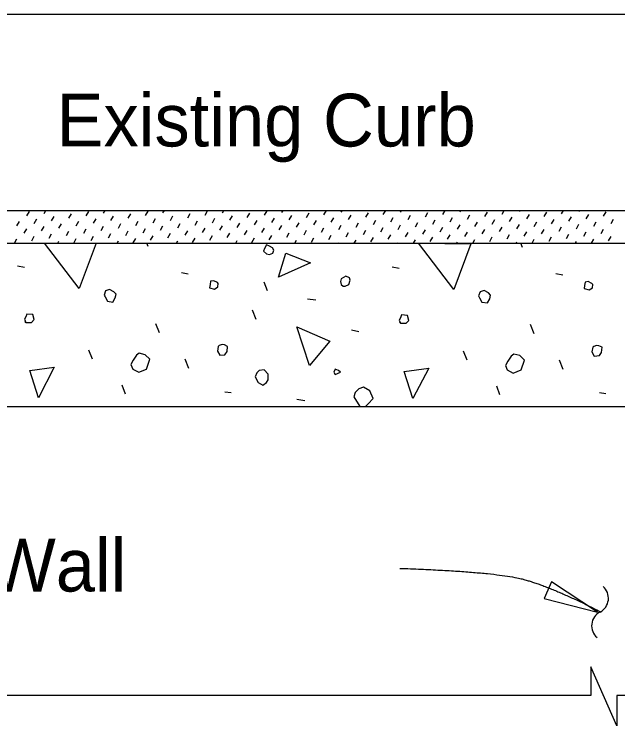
# Model space of a CAD drawing. Extents: x 2.6 to 35.7, y 1.7 to 23.4.
# Drawn here: x 11.926 to 14.234, y 5.942 to 8.663 of the extents above; entities that cross this region are included whole.
import ezdxf

# ---------------------------------------------------------------- set-up
doc = ezdxf.new("R2010")
doc.units = 0
for name, color, linetype in [('Dimension', 7, 'Continuous'), ('Miscellaneous', 7, 'Continuous'), ('TextStructures', 7, 'Continuous'), ('TrafBarrierConc', 7, 'Continuous')]:
    doc.layers.add(name, color=color, linetype=linetype)

msp = doc.modelspace()

# ---------------------------------------------------------------- linework, layer by layer
at = {"layer": 'Dimension'}
msp.add_lwpolyline([(14.1568, 6.3768), (13.9806, 6.4933), (13.952, 6.4288)], close=True, dxfattribs=at)
for points in [[(12.6311, 6.0586), (10.0672, 6.0586), (10.0672, 5.9424), (9.9678, 6.1674), (9.9678, 6.0586), (8.3596, 6.0586)], [(17.7044, 6.0586), (14.2297, 6.0586), (14.2297, 5.9424), (14.1304, 6.1674), (14.1304, 6.0586), (12.6311, 6.0586)]]:
    msp.add_lwpolyline(points, dxfattribs=at)
for centre, start, end in [((14.1386, 6.4303), 297.3915, 49.1187), ((14.1935, 6.3245), 117.3915, 229.1187)]:
    msp.add_arc(centre, 0.0596, start, end, dxfattribs=at)
msp.add_open_spline([(13.4009, 6.5444), (13.7659, 6.5314), (13.982, 6.4729), (14.1657, 6.3795)], degree=2, dxfattribs=at)
at = {"layer": 'Miscellaneous'}
for p, q in [((11.9745, 7.8919), (11.9842, 7.9087)), ((12.0408, 7.9016), (12.0476, 7.9134)), ((12.1071, 7.9113), (12.1083, 7.9134)), ((12.1354, 7.8831), (12.1451, 7.8999)), ((12.2017, 7.8928), (12.2114, 7.9096)), ((12.268, 7.9025), (12.2743, 7.9134)), ((12.3343, 7.9122), (12.3349, 7.9134)), ((12.3626, 7.8839), (12.3723, 7.9007)), ((12.4288, 7.8937), (12.4386, 7.9105)), ((12.4951, 7.9034), (12.5009, 7.9134)), ((12.5234, 7.8751), (12.5331, 7.8919)), ((12.5614, 7.9131), (12.5616, 7.9134)), ((12.5897, 7.8848), (12.5994, 7.9016)), ((12.656, 7.8946), (12.6657, 7.9113)), ((12.7223, 7.9043), (12.7276, 7.9134)), ((12.7506, 7.876), (12.7603, 7.8928)), ((12.8169, 7.8857), (12.8266, 7.9025)), ((12.8832, 7.8954), (12.8929, 7.9122)), ((12.9494, 7.9052), (12.9542, 7.9134)), ((12.9777, 7.8769), (12.9875, 7.8937)), ((13.044, 7.8866), (13.0537, 7.9034)), ((13.1103, 7.8963), (13.12, 7.9131)), ((13.1766, 7.906), (13.1809, 7.9134)), ((13.2049, 7.8778), (13.2146, 7.8946)), ((13.2712, 7.8875), (13.2809, 7.9043)), ((13.3375, 7.8972), (13.3469, 7.9134)), ((13.4038, 7.9069), (13.4075, 7.9134)), ((13.432, 7.8786), (13.4418, 7.8954)), ((13.4983, 7.8884), (13.5081, 7.9052)), ((13.5646, 7.8981), (13.5735, 7.9134)), ((13.6309, 7.9078), (13.6342, 7.9134)), ((13.6592, 7.8795), (13.6689, 7.8963)), ((13.7255, 7.8893), (13.7352, 7.906)), ((13.7918, 7.899), (13.8001, 7.9134)), ((13.8581, 7.9087), (13.8608, 7.9134)), ((13.8864, 7.8804), (13.8961, 7.8972)), ((13.9527, 7.8901), (13.9624, 7.9069)), ((14.0189, 7.8999), (14.0268, 7.9134)), ((14.0852, 7.9096), (14.0875, 7.9134)), ((14.1135, 7.8813), (14.1232, 7.8981)), ((14.1798, 7.891), (14.1895, 7.9078)), ((11.9365, 7.8539), (11.9462, 7.8707)), ((12.0028, 7.8636), (12.0125, 7.8804)), ((12.0691, 7.8733), (12.0788, 7.8901)), ((12.1637, 7.8548), (12.1734, 7.8716)), ((12.23, 7.8645), (12.2397, 7.8813)), ((12.2963, 7.8742), (12.306, 7.891)), ((12.3908, 7.8557), (12.4006, 7.8725)), ((12.4571, 7.8654), (12.4668, 7.8822)), ((12.618, 7.8565), (12.6277, 7.8733)), ((12.6843, 7.8663), (12.694, 7.8831)), ((12.7789, 7.8477), (12.7886, 7.8645)), ((12.8452, 7.8574), (12.8549, 7.8742)), ((12.9114, 7.8672), (12.9212, 7.8839)), ((13.006, 7.8486), (13.0157, 7.8654)), ((13.0723, 7.8583), (13.082, 7.8751)), ((13.1386, 7.868), (13.1483, 7.8848)), ((13.2332, 7.8495), (13.2429, 7.8663)), ((13.2995, 7.8592), (13.3092, 7.876)), ((13.3658, 7.8689), (13.3755, 7.8857)), ((13.4603, 7.8504), (13.4701, 7.8672)), ((13.5266, 7.8601), (13.5363, 7.8769)), ((13.5929, 7.8698), (13.6026, 7.8866)), ((13.6875, 7.8512), (13.6972, 7.868)), ((13.7538, 7.861), (13.7635, 7.8778)), ((13.8201, 7.8707), (13.8298, 7.8875)), ((13.9147, 7.8521), (13.9244, 7.8689)), ((13.9809, 7.8619), (13.9907, 7.8786)), ((14.0472, 7.8716), (14.057, 7.8884)), ((14.1418, 7.853), (14.1515, 7.8698)), ((14.2081, 7.8627), (14.2178, 7.8795)), ((11.9648, 7.8256), (11.9745, 7.8424)), ((12.0311, 7.8353), (12.0408, 7.8521)), ((12.0974, 7.8451), (12.1071, 7.8619)), ((12.192, 7.8265), (12.2017, 7.8433)), ((12.2583, 7.8362), (12.268, 7.853)), ((12.3245, 7.8459), (12.3343, 7.8627)), ((12.4191, 7.8274), (12.4288, 7.8442)), ((12.4854, 7.8371), (12.4951, 7.8539)), ((12.5517, 7.8468), (12.5614, 7.8636)), ((12.6463, 7.8283), (12.656, 7.8451)), ((12.7126, 7.838), (12.7223, 7.8548)), ((12.8734, 7.8291), (12.8832, 7.8459)), ((12.9397, 7.8389), (12.9494, 7.8557)), ((13.0343, 7.8203), (13.044, 7.8371)), ((13.1006, 7.83), (13.1103, 7.8468)), ((13.1669, 7.8398), (13.1766, 7.8565)), ((13.2615, 7.8212), (13.2712, 7.838)), ((13.3278, 7.8309), (13.3375, 7.8477)), ((13.394, 7.8406), (13.4038, 7.8574)), ((13.4886, 7.8221), (13.4983, 7.8389)), ((13.5549, 7.8318), (13.5646, 7.8486)), ((13.6212, 7.8415), (13.6309, 7.8583)), ((13.7158, 7.823), (13.7255, 7.8398)), ((13.7821, 7.8327), (13.7918, 7.8495)), ((13.8484, 7.8424), (13.8581, 7.8592)), ((13.9429, 7.8238), (13.9527, 7.8406)), ((14.0092, 7.8336), (14.0189, 7.8504)), ((14.0755, 7.8433), (14.0852, 7.8601)), ((14.1701, 7.8247), (14.1798, 7.8415)), ((11.9931, 7.7973), (12.0028, 7.8141)), ((12.0594, 7.807), (12.0691, 7.8238)), ((12.1257, 7.8168), (12.1354, 7.8336)), ((12.2202, 7.7982), (12.23, 7.815)), ((12.2865, 7.8079), (12.2963, 7.8247)), ((12.3528, 7.8177), (12.3626, 7.8345)), ((12.4474, 7.7991), (12.4571, 7.8159)), ((12.5137, 7.8088), (12.5234, 7.8256)), ((12.58, 7.8185), (12.5897, 7.8353)), ((12.6746, 7.8), (12.6843, 7.8168)), ((12.7409, 7.8097), (12.7506, 7.8265)), ((12.8071, 7.8194), (12.8169, 7.8362)), ((12.9017, 7.8009), (12.9114, 7.8177)), ((12.968, 7.8106), (12.9777, 7.8274)), ((13.1289, 7.8017), (13.1386, 7.8185)), ((13.1952, 7.8115), (13.2049, 7.8283)), ((13.2897, 7.7929), (13.2995, 7.8097)), ((13.356, 7.8026), (13.3658, 7.8194)), ((13.4223, 7.8124), (13.432, 7.8291)), ((13.5169, 7.7938), (13.5266, 7.8106)), ((13.5832, 7.8035), (13.5929, 7.8203)), ((13.6495, 7.8132), (13.6592, 7.83)), ((13.7441, 7.7947), (13.7538, 7.8115)), ((13.8104, 7.8044), (13.8201, 7.8212)), ((13.8766, 7.8141), (13.8864, 7.8309)), ((13.9712, 7.7956), (13.9809, 7.8124)), ((14.0375, 7.8053), (14.0472, 7.8221)), ((14.1038, 7.815), (14.1135, 7.8318)), ((14.1984, 7.7964), (14.2081, 7.8132)), ((11.9273, 7.7884), (11.9365, 7.8044)), ((12.0932, 7.7884), (12.0974, 7.7956)), ((12.154, 7.7885), (12.1637, 7.8053)), ((12.3199, 7.7884), (12.3245, 7.7964)), ((12.3811, 7.7894), (12.3908, 7.8062)), ((12.438, 7.775), (12.4331, 7.7884)), ((12.5465, 7.7884), (12.5517, 7.7973)), ((12.6083, 7.7903), (12.618, 7.807)), ((12.7125, 7.7884), (12.7126, 7.7885)), ((12.7732, 7.7884), (12.7789, 7.7982)), ((12.8354, 7.7911), (12.8452, 7.8079)), ((12.9392, 7.7884), (12.9397, 7.7894)), ((12.9998, 7.7884), (13.006, 7.7991)), ((13.0626, 7.792), (13.0723, 7.8088)), ((13.1658, 7.7884), (13.1669, 7.7903)), ((13.2265, 7.7884), (13.2332, 7.8)), ((13.3925, 7.7884), (13.394, 7.7911)), ((13.4531, 7.7884), (13.4603, 7.8009)), ((13.6191, 7.7884), (13.6212, 7.792)), ((13.6798, 7.7884), (13.6875, 7.8017)), ((13.8458, 7.7884), (13.8484, 7.7929)), ((13.8699, 7.7715), (13.8637, 7.7884)), ((13.9064, 7.7884), (13.9147, 7.8026)), ((14.0724, 7.7884), (14.0755, 7.7938)), ((14.1331, 7.7884), (14.1418, 7.8035)), ((11.9395, 7.7008), (11.966, 7.6955)), ((12.5653, 7.6761), (12.5918, 7.6707)), ((13.3714, 7.6973), (13.3979, 7.692)), ((13.9972, 7.6725), (14.0237, 7.6672)), ((12.8941, 7.6053), (12.8817, 7.6389)), ((13.0479, 7.5753), (13.0797, 7.5718)), ((12.8517, 7.4957), (12.8375, 7.5311)), ((12.4822, 7.4445), (12.4681, 7.4798)), ((13.2158, 7.4568), (13.2441, 7.4498)), ((13.9141, 7.4409), (13.9, 7.4763)), ((12.2259, 7.3437), (12.2117, 7.3791)), ((13.6578, 7.3402), (13.6436, 7.3755)), ((12.5936, 7.3084), (12.5794, 7.3437)), ((14.0255, 7.3048), (14.0113, 7.3402)), ((12.3514, 7.2111), (12.339, 7.2447)), ((13.7833, 7.2076), (13.7709, 7.2412)), ((12.7315, 7.22), (12.7562, 7.2164)), ((14.1634, 7.2164), (14.1881, 7.2129)), ((13.0072, 7.1917), (13.0373, 7.1864))]:
    msp.add_line(p, q, dxfattribs=at)
for points in [[(12.1746, 7.6142), (12.0422, 7.7884)], [(12.2397, 7.7884), (12.1746, 7.6142)], [(13.6065, 7.6106), (13.4722, 7.7874), (13.6719, 7.7857), (13.6065, 7.6106)], [(12.8906, 7.7468), (12.9029, 7.745), (12.9153, 7.7503), (12.9188, 7.7609), (12.9135, 7.7697), (12.9029, 7.7768), (12.8906, 7.7821), (12.8835, 7.768), (12.88, 7.7574), (12.8906, 7.7468)], [(12.9365, 7.6584), (12.9648, 7.7503), (13.0585, 7.7132), (12.9365, 7.6584)], [(13.184, 7.623), (13.1911, 7.623), (13.2052, 7.6301), (13.2105, 7.646), (13.2088, 7.6548), (13.1946, 7.6619), (13.1769, 7.6513), (13.1734, 7.6407), (13.1769, 7.6301), (13.184, 7.623)], [(12.6731, 7.6177), (12.6926, 7.6124), (12.7049, 7.6213), (12.7067, 7.6336), (12.7032, 7.6372), (12.689, 7.6442), (12.6767, 7.6425), (12.6749, 7.6301), (12.6731, 7.6177)], [(14.105, 7.6142), (14.1245, 7.6089), (14.1368, 7.6177), (14.1386, 7.6301), (14.1351, 7.6336), (14.1209, 7.6407), (14.1086, 7.6389), (14.1068, 7.6266), (14.105, 7.6142)], [(12.2736, 7.5824), (12.2824, 7.5664), (12.3037, 7.5629), (12.3125, 7.5788), (12.316, 7.593), (12.3072, 7.6018), (12.2913, 7.6106), (12.2754, 7.6053), (12.2701, 7.5894), (12.2736, 7.5824)], [(13.7055, 7.5788), (13.7143, 7.5629), (13.7356, 7.5594), (13.7444, 7.5753), (13.7479, 7.5894), (13.7391, 7.5983), (13.7232, 7.6071), (13.7073, 7.6018), (13.702, 7.5859), (13.7055, 7.5788)], [(11.9713, 7.4851), (11.9925, 7.4851), (12.0031, 7.4957), (11.9978, 7.5152), (11.9749, 7.517), (11.9713, 7.5063), (11.966, 7.4975), (11.9713, 7.4851), (11.9678, 7.4887)], [(13.4032, 7.4816), (13.4244, 7.4816), (13.435, 7.4922), (13.4297, 7.5116), (13.4067, 7.5134), (13.4032, 7.5028), (13.3979, 7.494), (13.4032, 7.4816), (13.3997, 7.4851)], [(13.055, 7.3207), (13.0072, 7.4675), (13.1327, 7.4127), (13.055, 7.3207)], [(12.7032, 7.3755), (12.712, 7.3596), (12.7315, 7.3614), (12.7403, 7.3738), (12.7421, 7.3932), (12.7297, 7.3985), (12.7209, 7.4003), (12.7102, 7.3967), (12.7067, 7.3932), (12.7032, 7.3755)], [(14.1351, 7.372), (14.1439, 7.3561), (14.1634, 7.3579), (14.1722, 7.3702), (14.174, 7.3897), (14.1616, 7.395), (14.1527, 7.3967), (14.1421, 7.3932), (14.1386, 7.3897), (14.1351, 7.372)], [(12.3797, 7.3066), (12.4027, 7.2942), (12.4327, 7.3066), (12.4451, 7.3437), (12.4274, 7.3614), (12.4044, 7.3667), (12.3938, 7.3596), (12.3814, 7.3402), (12.3726, 7.3243), (12.3797, 7.3066)], [(13.8116, 7.3031), (13.8345, 7.2907), (13.8646, 7.3031), (13.877, 7.3402), (13.8593, 7.3579), (13.8363, 7.3632), (13.8257, 7.3561), (13.8133, 7.3366), (13.8045, 7.3207), (13.8116, 7.3031)], [(12.0191, 7.197), (11.9855, 7.3013), (12.0792, 7.3137), (12.0191, 7.197)], [(12.8481, 7.2765), (12.8587, 7.2553), (12.8764, 7.2447), (12.8906, 7.2553), (12.8976, 7.2659), (12.8976, 7.2871), (12.8817, 7.3031), (12.8623, 7.3013), (12.8534, 7.2924), (12.8481, 7.2765)], [(13.154, 7.2854), (13.1734, 7.2942), (13.1663, 7.3013), (13.154, 7.3066), (13.1487, 7.2942), (13.154, 7.2854)], [(13.4509, 7.1935), (13.4174, 7.2977), (13.511, 7.3101), (13.4509, 7.1935)], [(13.2247, 7.2005), (13.2477, 7.1634), (13.2706, 7.1652), (13.2795, 7.174), (13.2989, 7.1935), (13.2865, 7.2235), (13.2618, 7.2376), (13.2441, 7.2306), (13.23, 7.2164), (13.2247, 7.2005)]]:
    msp.add_lwpolyline(points, dxfattribs=at)
at = {"layer": 'TrafBarrierConc'}
for p, q in [((8.4846, 8.6634), (17.4572, 8.6634)), ((8.4846, 7.9134), (17.9962, 7.9134)), ((8.4846, 7.7884), (17.9962, 7.7884)), ((8.4846, 7.1633), (17.9962, 7.1633))]:
    msp.add_line(p, q, dxfattribs=at)

# ---------------------------------------------------------------- texts
at = {"layer": 'TextStructures'}
for s, p in [('Existing Curb', (12.088, 8.1577)), ('Existing End Bent Wing Wall', (8.9388, 6.4557))]:
    msp.add_text(s, height=0.2016, dxfattribs=at).set_placement(p)

doc.saveas('drawing.dxf')
